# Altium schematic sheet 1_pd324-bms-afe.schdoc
size 848 x 601 mm; Symbol: Drawing-Symbol_A4; Device: Drawing-Symbol_A4; Company: 嘉立创EDA; Version: V1.0; Page Size: A4; @Project Name: PD324; @Page Count: 1; @Update Date: 2025-05-08; @Create Date: 2025-05-08; @Schematic Name: Schematic2; @Page No: 1; @Page Name: pd324-bms-afe; @Create Time: 17:02:18; @Update Time: 22:16:44; Width: 3304; Height: 2338; Region Start: 1; X Region Count: 6; Y Region Count: 4; Blade Width: 10; Title Block Position: 3; @Board Name: dc-cntl
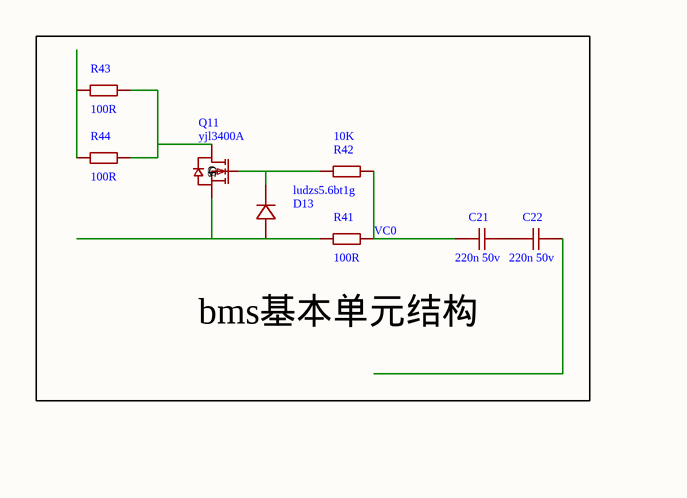
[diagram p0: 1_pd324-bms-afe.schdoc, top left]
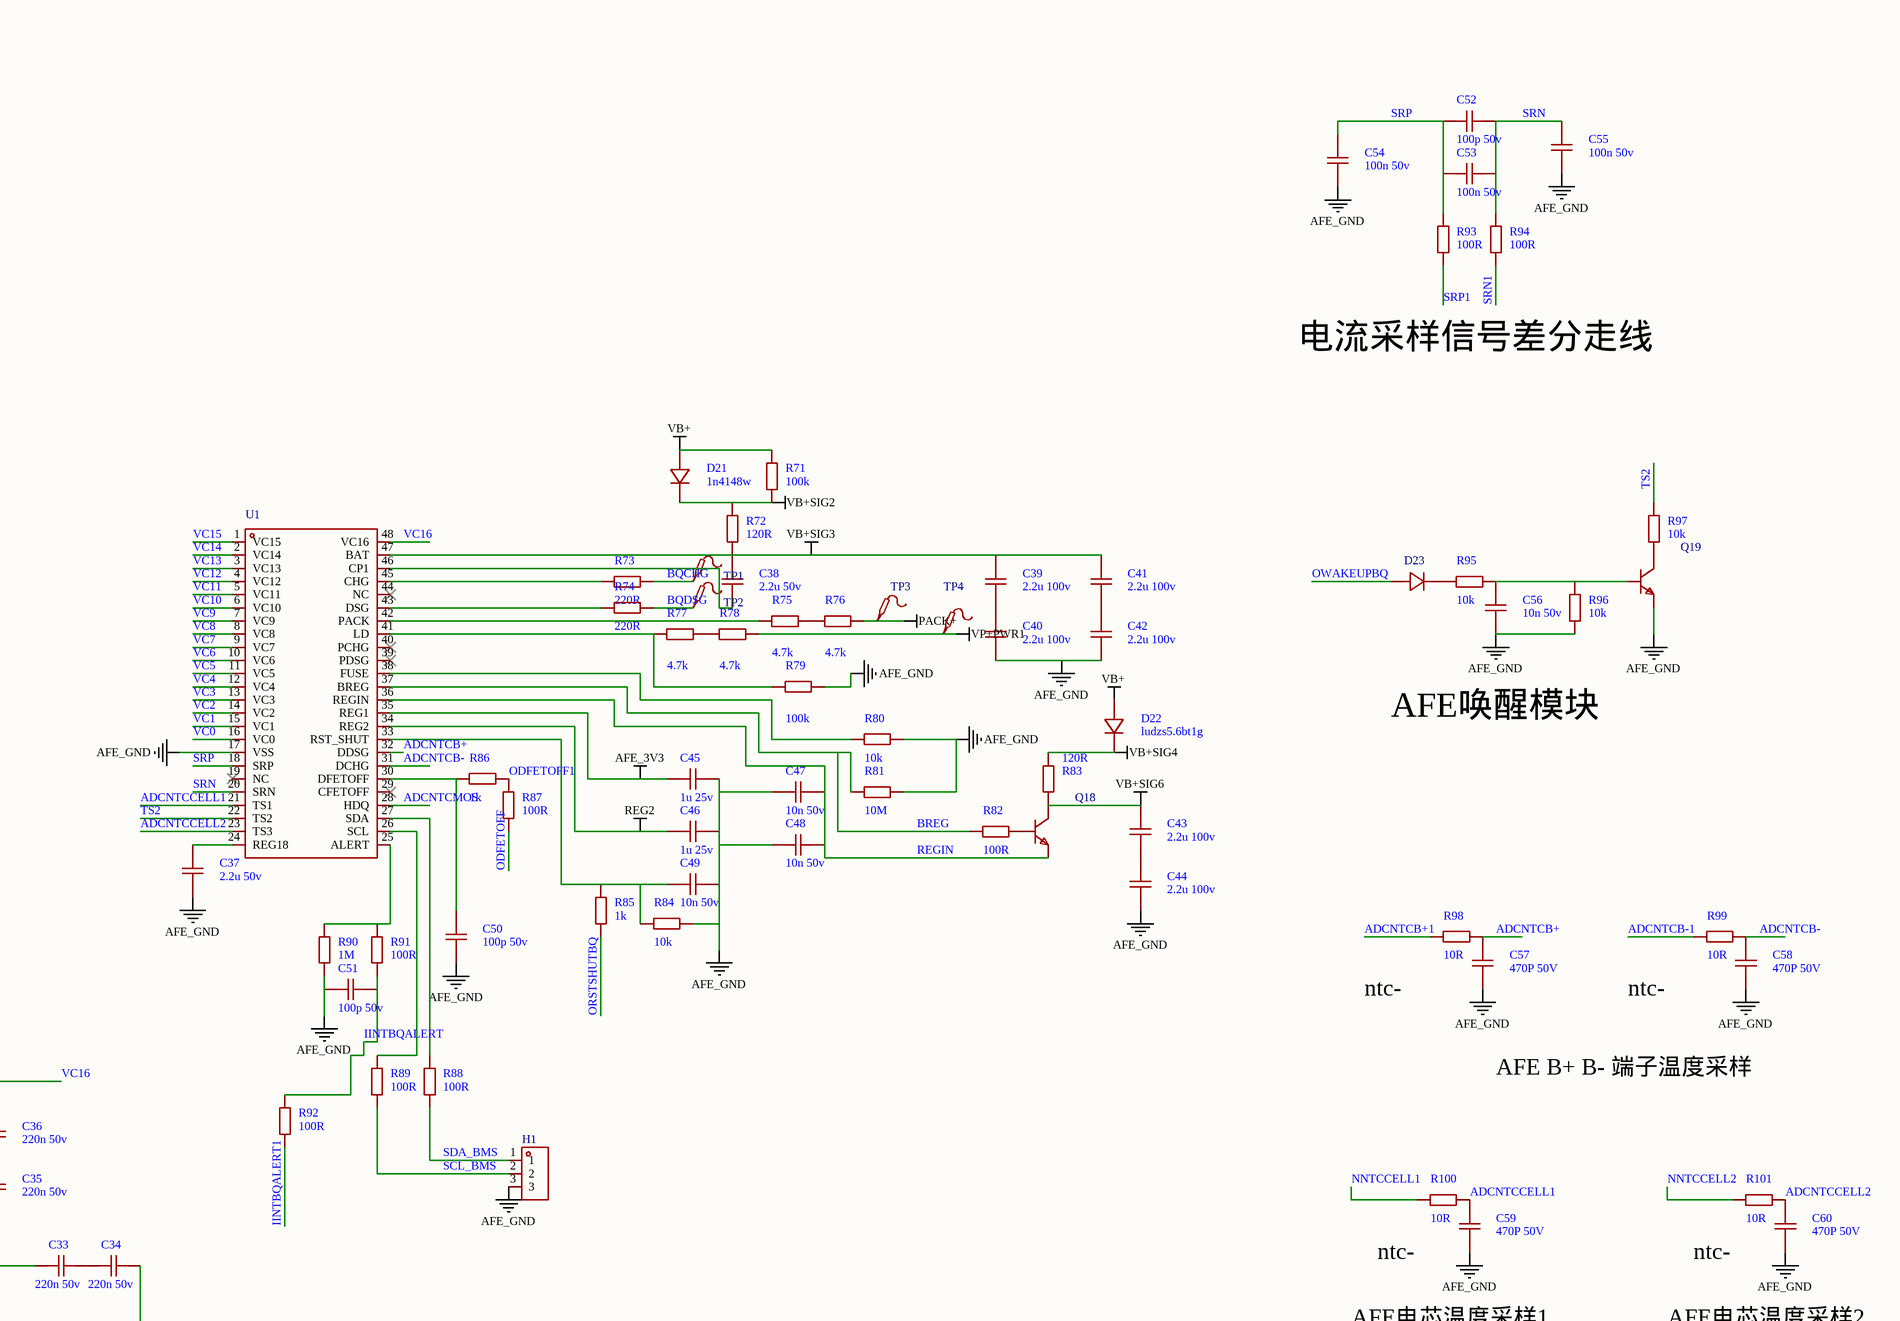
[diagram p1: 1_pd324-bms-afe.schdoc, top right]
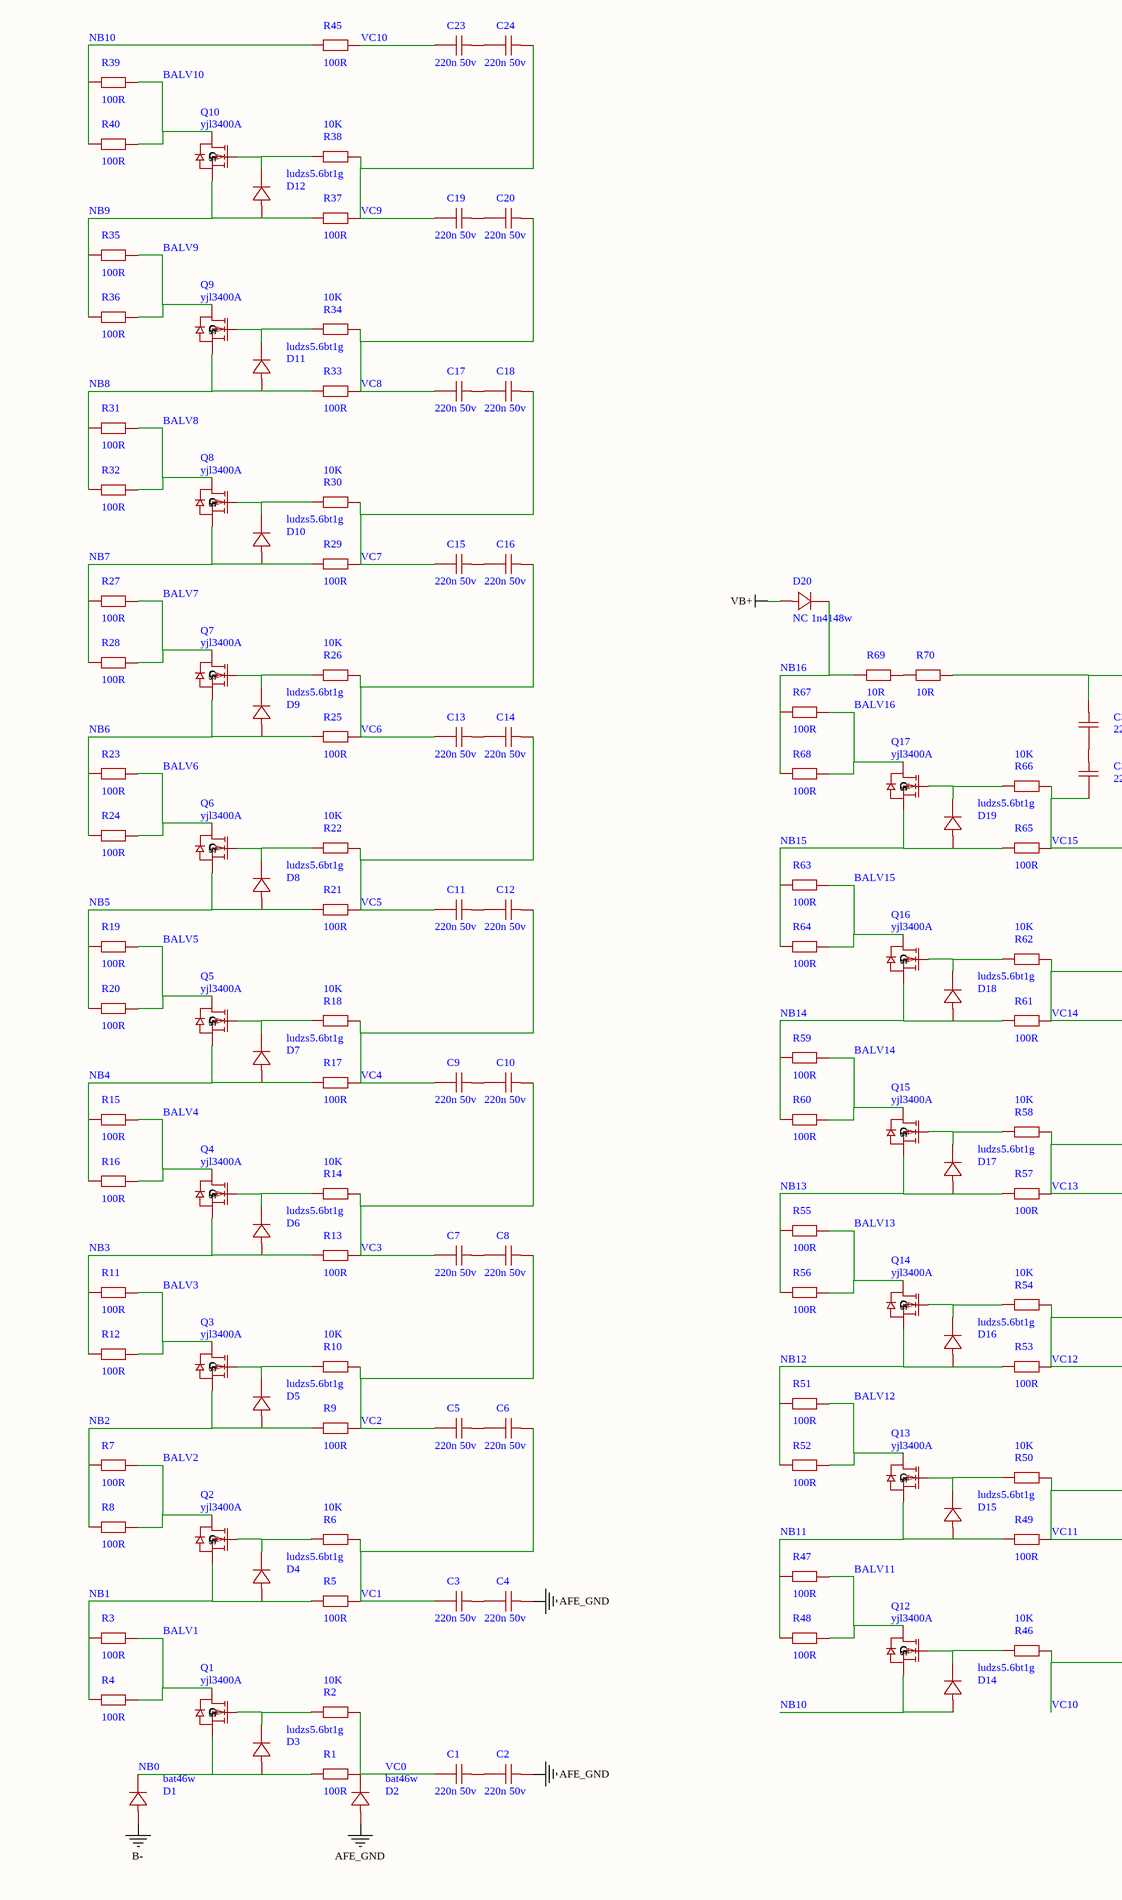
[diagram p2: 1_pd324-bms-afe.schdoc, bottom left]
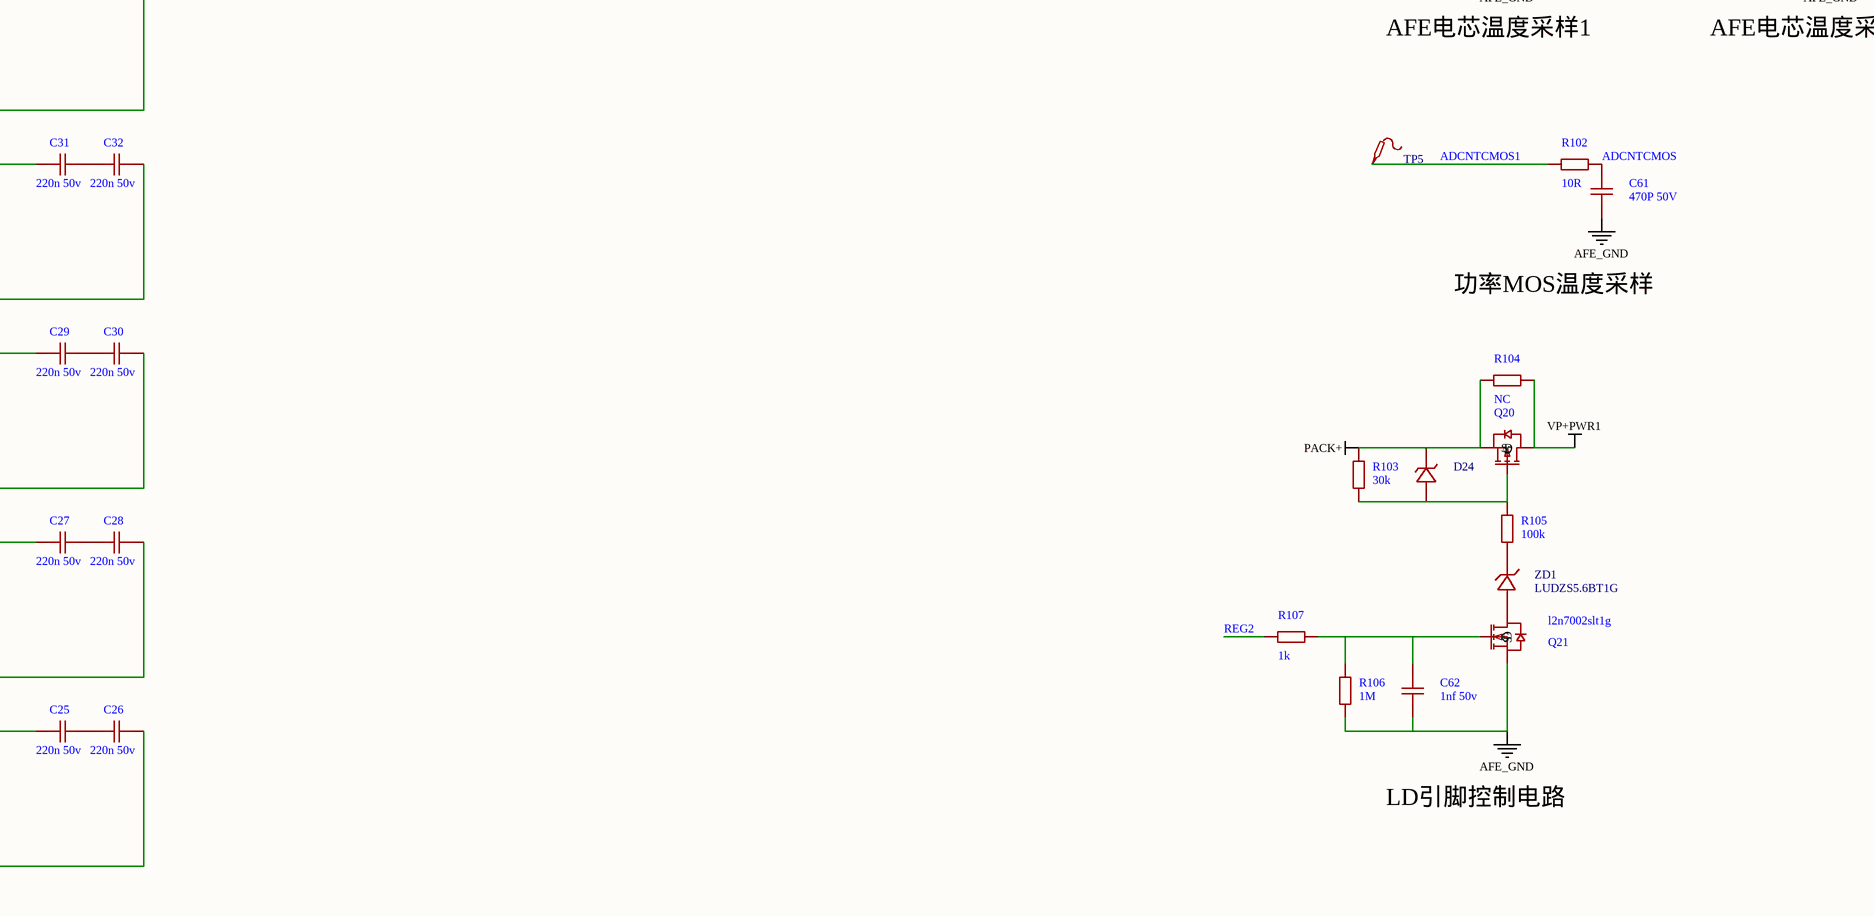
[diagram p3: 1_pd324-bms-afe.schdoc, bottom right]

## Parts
C1  220n 50v  [C0603]
C2  220n 50v  [C0603]
C3  220n 50v  [C0603]
C4  220n 50v  [C0603]
C5  220n 50v  [C0603]
C6  220n 50v  [C0603]
C7  220n 50v  [C0603]
C8  220n 50v  [C0603]
C9  220n 50v  [C0603]
C10  220n 50v  [C0603]
C11  220n 50v  [C0603]
C12  220n 50v  [C0603]
C13  220n 50v  [C0603]
C14  220n 50v  [C0603]
C15  220n 50v  [C0603]
C16  220n 50v  [C0603]
C17  220n 50v  [C0603]
C18  220n 50v  [C0603]
C19  220n 50v  [C0603]
C20  220n 50v  [C0603]
C21  220n 50v  [C0603]
C22  220n 50v  [C0603]
C23  220n 50v  [C0603]
C24  220n 50v  [C0603]
C25  220n 50v  [C0603]
C26  220n 50v  [C0603]
C27  220n 50v  [C0603]
C28  220n 50v  [C0603]
C29  220n 50v  [C0603]
C30  220n 50v  [C0603]
C31  220n 50v  [C0603]
C32  220n 50v  [C0603]
C33  220n 50v  [C0603]
C34  220n 50v  [C0603]
C35  220n 50v  [C0603]
C36  220n 50v  [C0603]
C37  2.2u 50v  [C0603]
C38  2.2u 50v  [C0603]
C39  2.2u 100v  [C0603]
C40  2.2u 100v  [C0603]
C41  2.2u 100v  [C0603]
C42  2.2u 100v  [C0603]
C43  2.2u 100v  [C0603]
C44  2.2u 100v  [C0603]
C45  1u 25v  [C0603]
C46  1u 25v  [C0603]
C47  10n 50v  [C0603]
C48  10n 50v  [C0603]
C49  10n 50v  [C0603]
C50  100p 50v  [C0603]
C51  100p 50v  [C0603]
C52  100p 50v  [C0603]
C53  100n 50v  [C0603]
C54  100n 50v  [C0603]
C55  100n 50v  [C0603]
C56  10n 50v  [C0603]
C57  470P 50V  [C0603]
C58  470P 50V  [C0603]
C59  470P 50V  [C0603]
C60  470P 50V  [C0603]
C61  470P 50V  [C0603]
C62  1nf 50v  [C0603]
D1  bat46w  [DO_1N4007]
D2  bat46w  [DO_1N4007]
D3  ludzs5.6bt1g  [DO_1N4007]
D4  ludzs5.6bt1g  [DO_1N4007]
D5  ludzs5.6bt1g  [DO_1N4007]
D6  ludzs5.6bt1g  [DO_1N4007]
D7  ludzs5.6bt1g  [DO_1N4007]
D8  ludzs5.6bt1g  [DO_1N4007]
D9  ludzs5.6bt1g  [DO_1N4007]
D10  ludzs5.6bt1g  [DO_1N4007]
D11  ludzs5.6bt1g  [DO_1N4007]
D12  ludzs5.6bt1g  [DO_1N4007]
D13  ludzs5.6bt1g  [DO_1N4007]
D14  ludzs5.6bt1g  [DO_1N4007]
D15  ludzs5.6bt1g  [DO_1N4007]
D16  ludzs5.6bt1g  [DO_1N4007]
D17  ludzs5.6bt1g  [DO_1N4007]
D18  ludzs5.6bt1g  [DO_1N4007]
D19  ludzs5.6bt1g  [DO_1N4007]
D20  NC 1n4148w  [DO_1N4007]
D21  1n4148w  [DO_1N4007]
D22  ludzs5.6bt1g  [DO_1N4007]
D23  1N4148W  [SOD-123_L2.7-W1.6-LS3.7-RD-1]  (value not drawn)
D24  BZT52C15  [SOD-123_L2.7-W1.7-LS3.8-RD]  (value not drawn)
H1  (no value)  [HDR-TH_3P-P2.54-V-M]
Q1  yjl3400A  [SOT-23-3_L2.9-W1.3-P1.90-LS2.4-BR]
Q2  yjl3400A  [SOT-23-3_L2.9-W1.3-P1.90-LS2.4-BR]
Q3  yjl3400A  [SOT-23-3_L2.9-W1.3-P1.90-LS2.4-BR]
Q4  yjl3400A  [SOT-23-3_L2.9-W1.3-P1.90-LS2.4-BR]
Q5  yjl3400A  [SOT-23-3_L2.9-W1.3-P1.90-LS2.4-BR]
Q6  yjl3400A  [SOT-23-3_L2.9-W1.3-P1.90-LS2.4-BR]
Q7  yjl3400A  [SOT-23-3_L2.9-W1.3-P1.90-LS2.4-BR]
Q8  yjl3400A  [SOT-23-3_L2.9-W1.3-P1.90-LS2.4-BR]
Q9  yjl3400A  [SOT-23-3_L2.9-W1.3-P1.90-LS2.4-BR]
Q10  yjl3400A  [SOT-23-3_L2.9-W1.3-P1.90-LS2.4-BR]
Q11  yjl3400A  [SOT-23-3_L2.9-W1.3-P1.90-LS2.4-BR]
Q12  yjl3400A  [SOT-23-3_L2.9-W1.3-P1.90-LS2.4-BR]
Q13  yjl3400A  [SOT-23-3_L2.9-W1.3-P1.90-LS2.4-BR]
Q14  yjl3400A  [SOT-23-3_L2.9-W1.3-P1.90-LS2.4-BR]
Q15  yjl3400A  [SOT-23-3_L2.9-W1.3-P1.90-LS2.4-BR]
Q16  yjl3400A  [SOT-23-3_L2.9-W1.3-P1.90-LS2.4-BR]
Q17  yjl3400A  [SOT-23-3_L2.9-W1.3-P1.90-LS2.4-BR]
Q18  BCX56-16Q  [SOT-89-3_L4.5-W2.5-P1.50-LS4.2-BR]  (value not drawn)
Q19  LMBT5551LT1G  [SOT-23-3_L2.9-W1.3-P1.90-LS2.4-BR]  (value not drawn)
Q20  (no value)  [AO3401A_SOT-23-3]
Q21  l2n7002slt1g  [SOT-23-3_L2.9-W1.3-P1.90-LS2.4-BR]
R1  100R  [R0603]
R2  10K  [R0603]
R3  100R  [R1206]
R4  100R  [R1206]
R5  100R  [R0603]
R6  10K  [R0603]
R7  100R  [R1206]
R8  100R  [R1206]
R9  100R  [R0603]
R10  10K  [R0603]
R11  100R  [R1206]
R12  100R  [R1206]
R13  100R  [R0603]
R14  10K  [R0603]
R15  100R  [R1206]
R16  100R  [R1206]
R17  100R  [R0603]
R18  10K  [R0603]
R19  100R  [R1206]
R20  100R  [R1206]
R21  100R  [R0603]
R22  10K  [R0603]
R23  100R  [R1206]
R24  100R  [R1206]
R25  100R  [R0603]
R26  10K  [R0603]
R27  100R  [R1206]
R28  100R  [R1206]
R29  100R  [R0603]
R30  10K  [R0603]
R31  100R  [R1206]
R32  100R  [R1206]
R33  100R  [R0603]
R34  10K  [R0603]
R35  100R  [R1206]
R36  100R  [R1206]
R37  100R  [R0603]
R38  10K  [R0603]
R39  100R  [R1206]
R40  100R  [R1206]
R41  100R  [R0603]
R42  10K  [R0603]
R43  100R  [R1206]
R44  100R  [R1206]
R45  100R  [R0603]
R46  10K  [R0603]
R47  100R  [R1206]
R48  100R  [R1206]
R49  100R  [R0603]
R50  10K  [R0603]
R51  100R  [R1206]
R52  100R  [R1206]
R53  100R  [R0603]
R54  10K  [R0603]
R55  100R  [R1206]
R56  100R  [R1206]
R57  100R  [R0603]
R58  10K  [R0603]
R59  100R  [R1206]
R60  100R  [R1206]
R61  100R  [R0603]
R62  10K  [R0603]
R63  100R  [R1206]
R64  100R  [R1206]
R65  100R  [R0603]
R66  10K  [R0603]
R67  100R  [R1206]
R68  100R  [R1206]
R69  10R  [R1206]
R70  10R  [R1206]
R71  100k  [R0603]
R72  120R  [R0603]
R73  220R  [R0603]
R74  220R  [R0603]
R75  4.7k  [R1206]
R76  4.7k  [R1206]
R77  4.7k  [R1206]
R78  4.7k  [R1206]
R79  100k  [R1206]
R80  10k  [R0603]
R81  10M  [R0603]
R82  100R  [R0603]
R83  value 120R  [R0603]
R84  10k  [R0603]
R85  1k  [R0603]
R86  1k  [R0603]
R87  100R  [R0603]
R88  100R  [R0603]
R89  100R  [R0603]
R90  1M  [R0603]
R91  100R  [R0603]
R92  100R  [R0603]
R93  100R  [R0603]
R94  100R  [R0603]
R95  10k  [R0603]
R96  10k  [R0603]
R97  10k  [R0603]
R98  10R  [R0603]
R99  10R  [R0603]
R100  10R  [R0603]
R101  10R  [R0603]
R102  10R  [R0603]
R103  30k  [R0603]
R104  NC  [R1206]
R105  100k  [R0603]
R106  1M  [R0603]
R107  1k  [R0603]
TP1  (no value)  [Test-Point-0.5mm]
TP2  (no value)  [Test-Point-0.5mm]
TP3  (no value)  [Test-Point-0.5mm]
TP4  (no value)  [Test-Point-0.5mm]
TP5  (no value)  [Test-Point-0.5mm]
U1  BQ76952PFBR  [TQFP-48_L7.0-W7.0-P0.50-LS9.0-BL]  (value not drawn)
ZD1  LUDZS5.6BT1G  [SOD-323_L1.8-W1.3-LS2.5-RD]

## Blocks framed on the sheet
bms基本单元结构: C21 C22 D13 Q11 R41-R44

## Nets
AFE_3V3: C45.2 U1.35(REG1)
AFE_GND: C2.2 C4.2 C37.1 C40.1 C42.1 C44.1 C45.1 C46.1 C47.2 C48.2 C49.1 C50.2 C51.1 C54.2 C55.2 C56.2 C57.1 C58.1 C59.1 C60.1 C61.1 C62.1 D2.2(A) H1.3 Q19.2(E) Q21.2(S) R79.2 R80.2 R81.2 R84.1 R90.1 R96.2 R106.1 U1.17(VSS)
B-: D1.2(A)
PACK+: D24.1(K) Q20.2(S) R76.2 R103.2 R104.1 TP3.1
REG2: C46.2 R107.2 U1.34(REG2)
VB+: D20.2(A) D21.2(A) D22.2(A) R71.2
VB+SIG2: D21.1(K) R71.1 R72.2
VB+SIG3: C38.2 C39.2 C41.2 R72.1 U1.47(BAT)
VB+SIG4: D22.1(K) R83.2
VB+SIG6: C43.2 Q18.2(C) R83.1
VP+PWR1: Q20.3(D) R78.2 R104.2 TP4.1
ADCNTCB+: C57.2 R98.2 U1.32(DDSG)
ADCNTCB+1: R98.1
ADCNTCB-: C58.2 R99.2 U1.31(DCHG)
ADCNTCB-1: R99.1
ADCNTCCELL1: C59.2 R100.2 U1.21(TS1)
ADCNTCCELL2: C60.2 R101.2 U1.23(TS3)
ADCNTCMOS: C61.2 R102.2 U1.28(HDQ)
ADCNTCMOS1: R102.1 TP5.1
BALV1: Q1.3(D) R3.2 R4.2
BALV2: Q2.3(D) R7.2 R8.2
BALV3: Q3.3(D) R11.2 R12.2
BALV4: Q4.3(D) R15.2 R16.2
BALV5: Q5.3(D) R19.2 R20.2
BALV6: Q6.3(D) R23.2 R24.2
BALV7: Q7.3(D) R27.2 R28.2
BALV8: Q8.3(D) R31.2 R32.2
BALV9: Q9.3(D) R35.2 R36.2
BALV10: Q10.3(D) R39.2 R40.2
BALV11: Q12.3(D) R47.2 R48.2
BALV12: Q13.3(D) R51.2 R52.2
BALV13: Q14.3(D) R55.2 R56.2
BALV14: Q15.3(D) R59.2 R60.2
BALV15: Q16.3(D) R63.2 R64.2
BALV16: Q17.3(D) R67.2 R68.2
BQCHG: R73.1 TP1.1
BQDSG: R74.1 TP2.1
BREG: R81.1 R82.1 U1.37(BREG)
IINTBQALERT: C51.2 R91.1 R92.2
IINTBQALERT1: R92.1
NB0: D1.1(K) D3.2(A) Q1.2(S) R1.1
NB1: D4.2(A) Q2.2(S) R3.1 R4.1 R5.1
NB2: D5.2(A) Q3.2(S) R7.1 R8.1 R9.1
NB3: D6.2(A) Q4.2(S) R11.1 R12.1 R13.1
NB4: D7.2(A) Q5.2(S) R15.1 R16.1 R17.1
NB5: D8.2(A) Q6.2(S) R19.1 R20.1 R21.1
NB6: D9.2(A) Q7.2(S) R23.1 R24.1 R25.1
NB7: D10.2(A) Q8.2(S) R27.1 R28.1 R29.1
NB8: D11.2(A) Q9.2(S) R31.1 R32.1 R33.1
NB9: D12.2(A) Q10.2(S) R35.1 R36.1 R37.1
NB10: D14.2(A) Q12.2(S) R39.1 R40.1 R45.1
NB11: D15.2(A) Q13.2(S) R47.1 R48.1 R49.1
NB12: D16.2(A) Q14.2(S) R51.1 R52.1 R53.1
NB13: D17.2(A) Q15.2(S) R55.1 R56.1 R57.1
NB14: D18.2(A) Q16.2(S) R59.1 R60.1 R61.1
NB15: D19.2(A) Q17.2(S) R63.1 R64.1 R65.1
NB16: D20.1(K) R67.1 R68.1 R69.1
NNTCCELL1: R100.1
NNTCCELL2: R101.1
ODFETOFF: R87.1
ODFETOFF1: R86.2 R87.2
ORSTSHUTBQ: R85.2
OWAKEUPBQ: D23.2(A)
REGIN: C47.1 C48.1 Q18.3(E) U1.36(REGIN)
SCL_BMS: H1.2 R89.1
SDA_BMS: H1.1 R88.1
SRN: C52.1 C53.1 C55.1 R94.2 U1.20(SRN)
SRN1: R94.1
SRP: C52.2 C53.2 C54.1 R93.2 U1.18(SRP)
SRP1: R93.1
TS2: R97.1 U1.22(TS2)
VC0: C1.1 C21.1 D2.1(K) R1.2 R2.2 R41.2 R42.2 U1.16(VC0)
VC1: C3.1 C6.2 R5.2 R6.2 U1.15(VC1)
VC2: C5.1 C8.2 R9.2 R10.2 U1.14(VC2)
VC3: C7.1 C10.2 R13.2 R14.2 U1.13(VC3)
VC4: C9.1 C12.2 R17.2 R18.2 U1.12(VC4)
VC5: C11.1 C14.2 R21.2 R22.2 U1.11(VC5)
VC6: C13.1 C16.2 R25.2 R26.2 U1.10(VC6)
VC7: C15.1 C18.2 R29.2 R30.2 U1.9(VC7)
VC8: C17.1 C20.2 R33.2 R34.2 U1.8(VC8)
VC9: C19.1 C24.2 R37.2 R38.2 U1.7(VC9)
VC10: C23.1 C26.2 R45.2 R46.2 U1.6(VC10)
VC11: C25.1 C28.2 R49.2 R50.2 U1.5(VC11)
VC12: C27.1 C30.2 R53.2 R54.2 U1.4(VC12)
VC13: C29.1 C32.2 R57.2 R58.2 U1.3(VC13)
VC14: C31.1 C34.2 R61.2 R62.2 U1.2(VC14)
VC15: C33.1 C35.1 R65.2 R66.2 U1.1(VC15)
VC16: C36.2 R70.2 U1.48(VC16)
NetC1_2: C1.2 C2.1
NetC3_2: C3.2 C4.1
NetC5_2: C5.2 C6.1
NetC7_2: C7.2 C8.1
NetC9_2: C9.2 C10.1
NetC11_2: C11.2 C12.1
NetC13_2: C13.2 C14.1
NetC15_2: C15.2 C16.1
NetC17_2: C17.2 C18.1
NetC19_2: C19.2 C20.1
NetC21_2: C21.2 C22.1
NetC23_2: C23.2 C24.1
NetC25_2: C25.2 C26.1
NetC27_2: C27.2 C28.1
NetC29_2: C29.2 C30.1
NetC31_2: C31.2 C32.1
NetC33_2: C33.2 C34.1
NetC35_2: C35.2 C36.1
NetC37_2: C37.2 U1.24(REG18)
NetC38_1: C38.1 U1.46(CP1)
NetC39_1: C39.1 C40.2
NetC41_1: C41.1 C42.2
NetC43_1: C43.1 C44.2
NetC49_2: C49.2 R84.2 R85.1 U1.33(RST_SHUT)
NetC50_1: C50.1 R86.1 U1.30(DFETOFF)
NetC56_1: C56.1 Q19.1(B) R95.1 R96.1
NetC62_2: C62.2 Q21.1(G) R106.2 R107.1
NetD3_1: D3.1(K) Q1.1(G) R2.1
NetD4_1: D4.1(K) Q2.1(G) R6.1
NetD5_1: D5.1(K) Q3.1(G) R10.1
NetD6_1: D6.1(K) Q4.1(G) R14.1
NetD7_1: D7.1(K) Q5.1(G) R18.1
NetD8_1: D8.1(K) Q6.1(G) R22.1
NetD9_1: D9.1(K) Q7.1(G) R26.1
NetD10_1: D10.1(K) Q8.1(G) R30.1
NetD11_1: D11.1(K) Q9.1(G) R34.1
NetD12_1: D12.1(K) Q10.1(G) R38.1
NetD13_1: D13.1(K) Q11.1(G) R42.1
NetD13_2: D13.2(A) Q11.2(S) R41.1
NetD14_1: D14.1(K) Q12.1(G) R46.1
NetD15_1: D15.1(K) Q13.1(G) R50.1
NetD16_1: D16.1(K) Q14.1(G) R54.1
NetD17_1: D17.1(K) Q15.1(G) R58.1
NetD18_1: D18.1(K) Q16.1(G) R62.1
NetD19_1: D19.1(K) Q17.1(G) R66.1
NetD23_1: D23.1(K) R95.2
NetD24_2: D24.2(A) Q20.1(G) R103.1 R105.2
NetQ11_3: Q11.3(D) R43.2 R44.2
NetQ18_1: Q18.1(B) R82.2
NetQ19_3: Q19.3(C) R97.2
NetQ21_3: Q21.3(D) ZD1.2(A)
NetR43_1: R43.1 R44.1
NetR69_2: R69.2 R70.1
NetR73_2: R73.2 U1.45(CHG)
NetR74_2: R74.2 U1.43(DSG)
NetR75_1: R75.1 U1.42(PACK)
NetR75_2: R75.2 R76.1
NetR77_1: R77.1 R79.1 U1.41(LD)
NetR77_2: R77.2 R78.1
NetR80_1: R80.1 U1.38(FUSE)
NetR88_2: R88.2 U1.27(SDA)
NetR89_2: R89.2 U1.26(SCL)
NetR90_2: R90.2 R91.2 U1.25(ALERT)
NetR105_1: R105.1 ZD1.1(K)

Not connected (* = marked no-connect by the designer): C22 2; U1 19(NC)* 29(CFETOFF)* 39(PDSG)* 40(PCHG)* 44(NC)*

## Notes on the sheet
- 电流采样信号差分走线
- AFE唤醒模块
- ntc-
- AFE B+ B- 端子温度采样
- AFE电芯温度采样1
- AFE电芯温度采样2
- 功率MOS温度采样
- LD引脚控制电路

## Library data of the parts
C1-C62 = CAP_0603: Symbol: CapAcitance; Convert to PCB: yes
D1-D22 = D_1N4007A: Add into BOM: yes
D23 = 1N4148W: Manufacturer: YONGYUTAI(永裕泰); Symbol: 1N4148W_C2892570; Add into BOM: yes; Diode Configuration: 独立式; Forward Voltage (Vf@If): 1.25V@100mA; Rectified Current: 150mA; Reverse Leakage Current (Ir): 5uA@75V; Reverse Recovery Time (trr): 4ns
D24 = BZT52C15: Manufacturer: TWGMC(台湾迪嘉); Symbol: BZT52C15_C727006; Add into BOM: yes; Diode Configuration: 独立式; Zener Voltage (Nom): 15V; Reverse Leakage Current (Ir): 100nA@10.5V; Zener Voltage (Range): 13.8V~15.6V; Power Dissipation: 500mW; Zener Impedance (Zzt): 30Ω
H1 = HDR-M_2.54_1x3P: Symbol: PZ254V-11-03P_C2937625; Convert to PCB: yes
Q1-Q17 Q21 = AO3400A_N: Symbol: N_MOS; Add into BOM: yes
Q18 = BCX56-16Q: Manufacturer: YANGJIE(扬杰); Add into BOM: yes; type: NPN; Current - Collector(Ic): 1A; Collector - Emitter Voltage VCEO: 80V; Pd - Power Dissipation: 500mW; DC Current Gain: 40@5mA,2V; Transition frequency(fT): 130MHz; Current - Collector Cutoff: 100nA; Vce Saturation(VCE(sat)): 500mV
Q19 = LMBT5551LT1G: Manufacturer: LRC(乐山无线电); Add into BOM: yes; type: NPN; Current - Collector(Ic): 600mA; Collector - Emitter Voltage VCEO: 160V; Pd - Power Dissipation: 225mW; DC Current Gain: 80@10mA,5.0V; Current - Collector Cutoff: 50nA; Vce Saturation(VCE(sat)): 200mV
Q20 = AO3401A_P: Symbol: P_MOS; Add into BOM: yes
R1 R5 R9 R13 R17 R21 R25 R29 R33 R37 R41 R45 R49 R53 R57 R61 R65 R71-R74 R81 R82 = Res_0603: Symbol: 电阻; Convert to PCB: yes; Value: 10K
R2 R6 R10 R14 R18 R22 R26 R30 R34 R38 R42 R46 R50 R54 R58 R62 R66 R80 R83-R86 R90-R103 R105-R107 = Res_0603: Symbol: 电阻; Convert to PCB: yes
R3 R4 R7 R8 R11 R12 R15 R16 R19 R20 R23 R24 R27 R28 R31 R32 R35 R36 R39 R40 R43 R44 R47 R48 R51 R52 R55 R56 R59 R60 R63 R64 R67-R70 R75-R79 R104 = Res_1206: Symbol: 电阻; Add into BOM: yes
R87-R89 = Res_0603: Symbol: 电阻; Convert to PCB: yes; Value: 1k
TP1-TP5 = Test-Point: Add into BOM: yes
U1 = BQ76952PFBR: Manufacturer: TI(德州仪器); Add into BOM: yes; Type of Battery: 锂离子/聚合物; Number of Cells: 3~16
ZD1 = LUDZS5.6BT1G: Manufacturer: LRC(乐山无线电); Add into BOM: yes; Diode Configuration: 独立式; Reverse Leakage Current (Ir): 1uA@2.5V; Zener Voltage (Range): 5.49V~5.73V; Power Dissipation: 200mW; Zener Impedance (Zzt): 60Ω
